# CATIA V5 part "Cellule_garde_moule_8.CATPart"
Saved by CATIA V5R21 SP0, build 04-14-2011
Part number: Moule_cellule_garde.1
Bounding box of the stored display mesh (mm): x -18 to 18, y -85 to 85, z -20 to 0
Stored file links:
  C:\Users\zerma\Pictures\Stage Stomate\Moule_4 pas utiliser\Cellule_garde_moule_8.CATPart
  Product1.CATProduct
  C:\Users\zerma\Pictures\Moule\Moule_v1.CATPart
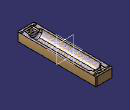
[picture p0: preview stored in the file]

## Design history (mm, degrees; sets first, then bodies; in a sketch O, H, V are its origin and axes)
Body1 (main body)
  Sketch1 on yz-plane, origin (0, 0, 0), H (0, 1, 0), V (0, 0, 1)
    line L1 (-95, -12.5) -> (95, -12.5)
    point P1 (-95, -12.5)
    line L2 (-100, -17.5) -> (100, -17.5)
    point P3 (-100, -17.5)
    line L3 (-95, -12.5) -> (-95, 0)
    point P5 (-95, 0)
    line L4 (-100, -17.5) -> (-100, 0)
    point P6 (-100, 0)
    line L5 (-95, 0) -> (-100, 0)
    point P7 (100, 0)
    point P8 (100, -17.5)
    line L6 (100, -17.5) -> (100, 0)
    point P9 (95, 0)
    line L7 (95, 0) -> (100, 0)
    point P10 (95, -12.5)
    line L8 (95, -12.5) -> (95, 0)
    distance L1 H = 12.5
    distance L1 L2 = 5
    distance L4 L3 = 5
    length L1 = 190
    length L2 = 200
    distance V L3 = 95
    horizontal: L1 H, L2 H, L5 H
    vertical: L3 V, L4 V
    symmetry: P6 P7 V, P3 P8 V, L4 L6 V, P5 P9 V, L5 L7 V, P1 P10 V, L3 L8 V
    coincidence: L5 H
  Shaft1: profile Sketch1, axis Sketch1.H, angle 360
  Sketch2 on face of Shaft1 from Sketch1.L4, origin (0, -100, 0), H (1, 0, 0), V (0, 0, 1)
    line L1 (-10, 2.5) -> (10, 2.5)
    line L2 (10, 2.5) -> (10, -2.5)
    line L3 (10, -2.5) -> (-10, -2.5)
    line L4 (-10, -2.5) -> (-10, 2.5)
    length L2 = 5
    length L1 = 20
    horizontal: L1 H, L3 H
    vertical: L2 V, L4 V
    symmetry: L3 L1 H, L4 L2 V
  Pad1: profile Sketch2, direction (0, -1, 0), length 15
  Sketch3 on face of Pad1 from Sketch2.L1, origin (0, 0, 2.5), H (1, 0, 0), V (0, 1, 0)
    circle A1 centre (0, -107.5) radius 2.5
    point P1 (0, -107.5)
    reference intersected line E1 (17.3205, -100) -> (-17.3205, -100) from face of Shaft1 from Sketch1.L4
    radius A1 = 2.5
    distance P1 E1 = 7.5
    coincidence: P1 V
  Pocket1: profile Sketch3, direction (0, 0, -1), length 5, mirrored extent
  Fillet1: radius 2, on edge [face of Pad1 from Sketch2.L4 | end face of Pad1]; edge [face of Pad1 from Sketch2.L1 | end face of Pad1]; edge [face of Pad1 from Sketch2.L3 | end face of Pad1]; edge [face of Pad1 from Sketch2.L2 | end face of Pad1]; edge [face of Pad1 from Sketch2.L2 | face of Pad1 from Sketch2.L3]; edge [face of Shaft1 from Sketch1.L4 | face of Pad1 from Sketch2.L3]; edge [face of Pad1 from Sketch2.L3 | face of Pad1 from Sketch2.L4]; edge [face of Pocket1 from Sketch3.A1 | face of Pad1 from Sketch2.L3]; edge [face of Pad1 from Sketch2.L4 | face of Pad1 from Sketch2.L1]; edge [face of Pad1 from Sketch2.L1 | face of Pad1 from Sketch2.L2]; edge [face of Shaft1 from Sketch1.L4 | face of Pad1 from Sketch2.L1]; edge [face of Shaft1 from Sketch1.L4 | face of Pad1 from Sketch2.L4]; edge [face of Shaft1 from Sketch1.L4 | face of Pad1 from Sketch2.L2]; face of Pad1 from Sketch2.L1
  Mirror1: of Pad1, Pocket1, Fillet1, about zx-plane
  Fillet2: radius 4, on edge [face of Shaft1 from Sketch1.L2 | face of Shaft1 from Sketch1.L6]; edge [face of Shaft1 from Sketch1.L4 | face of Shaft1 from Sketch1.L2]
Body2
  Sketch4 on xy-plane, origin (0, 0, 0), H (1, 0, 0), V (0, 1, 0)
    line L1 (18, 85) -> (18, -85)
    line L2 (18, -85) -> (-18, -85)
    line L3 (-18, -85) -> (-18, 85)
    line L4 (-18, 85) -> (18, 85)
    length L4 = 36
    length L1 = 170
    vertical: L1 V, L3 V
    horizontal: L2 H, L4 H
    equidistance: L1 L3 O, L2 L4 O
  Pad2: profile Sketch4, direction (0, 0, -1), length 20
  Sketch5 on end face of Pad2, origin (0, 0, -20), H (1, 0, 0), V (0, -1, 0)
    circle A1 centre (14, 79) radius 2.25
    point P1 (14, 79)
    circle A2 centre (14, -79) radius 2.25
    circle A3 centre (-14, 79) radius 2.25
    circle A4 centre (-14, -79) radius 2.25
    reference projected line E1 (18, 120) -> (18, -120) from edge [end face of Pad2 | face of Pad2 from Sketch4.L1]
    reference projected line E2 (-30, 85) -> (30, 85) from edge [end face of Pad2 | face of Pad2 from Sketch4.L2]
    radius A1 = 2.25
    distance P1 E1 = 4
    distance P1 E2 = 6
    symmetry: A1 A2 H, A1 A3 V, A3 A4 H
  Pocket2: profile Sketch5, direction (0, 0, 1), length 50, mirrored extent
  Chamfer1: length 2, angle 45, on edge [face of Pad2 from Sketch4.L4 | face of Pad2 from Sketch4.L3]; edge [end face of Pad2 | face of Pad2 from Sketch4.L4]; edge [end face of Pad2 | face of Pad2 from Sketch4.L3]; edge [face of Pad2 from Sketch4.L1 | face of Pad2 from Sketch4.L4]; edge [end face of Pad2 | face of Pad2 from Sketch4.L1]; edge [end face of Pad2 | face of Pad2 from Sketch4.L2]; edge [face of Pad2 from Sketch4.L2 | face of Pad2 from Sketch4.L1]; edge [face of Pad2 from Sketch4.L3 | face of Pad2 from Sketch4.L2]
  Body3
    Sketch6 on yz-plane, origin (0, 0, 0), H (0, 1, 0), V (0, 0, 1)
      line L1 (-61, -8) -> (61, -8)
      point P1 (-61, -8)
      point P2 (61, -8)
      line L2 (-66, -13.5) -> (66, -13.5)
      point P3 (-66, -13.5)
      point P4 (66, -13.5)
      line L3 (-61, -8) -> (-61, 0)
      point P5 (-61, 0)
      line L4 (-66, -13.5) -> (-66, 0)
      point P6 (-66, 0)
      line L5 (-61, 0) -> (-66, 0)
      point P7 (66, 0)
      point P8 (66, -13.5)
      line L6 (66, -13.5) -> (66, 0)
      point P9 (61, 0)
      line L7 (61, 0) -> (66, 0)
      point P10 (61, -8)
      line L8 (61, -8) -> (61, 0)
      distance L1 H = 8
      distance L1 L2 = 5.5
      distance L4 L3 = 5
      distance V L3 = 61
      horizontal: L1 H, L2 H, L5 H
      vertical: L3 V, L4 V
      symmetry: P6 P7 V, P3 P8 V, L4 L6 V, P5 P9 V, L5 L7 V, P1 P10 V, L3 L8 V
      coincidence: L5 H, P4 P8, P2 P10
    Shaft2: profile Sketch6, axis Sketch6.H, angle 360
    Sketch7 on face of Shaft2 from Sketch6.L4, origin (0, -66, 0), H (1, 0, 0), V (0, 0, 1)
      line L1 (-10, 2.5) -> (10, 2.5)
      line L2 (10, 2.5) -> (10, -2.5)
      line L3 (10, -2.5) -> (-10, -2.5)
      line L4 (-10, -2.5) -> (-10, 2.5)
      length L2 = 5
      length L1 = 20
      horizontal: L1 H, L3 H
      vertical: L2 V, L4 V
      symmetry: L3 L1 H, L4 L2 V
    Pad3: profile Sketch7, direction (0, -1, 0), length 15
    Sketch8 on face of Pad3 from Sketch7.L1, origin (0, 0, 2.5), H (1, 0, 0), V (0, 1, 0)
      circle A1 centre (0, -73.5) radius 2.5
      point P1 (0, -73.5)
      reference intersected line E1 (13.2665, -66) -> (-13.2665, -66) from face of Shaft2 from Sketch6.L4
      radius A1 = 2.5
      distance P1 E1 = 7.5
      coincidence: P1 V
    Pocket3: profile Sketch8, direction (0, 0, -1), length 5, mirrored extent
    Fillet3: radius 2, on edge [face of Pad3 from Sketch7.L4 | end face of Pad3]; edge [face of Pad3 from Sketch7.L1 | end face of Pad3]; edge [face of Pad3 from Sketch7.L3 | end face of Pad3]; edge [face of Pad3 from Sketch7.L2 | end face of Pad3]; edge [face of Pad3 from Sketch7.L2 | face of Pad3 from Sketch7.L3]; edge [face of Shaft2 from Sketch6.L4 | face of Pad3 from Sketch7.L3]; edge [face of Pad3 from Sketch7.L3 | face of Pad3 from Sketch7.L4]; edge [face of Pocket3 from Sketch8.A1 | face of Pad3 from Sketch7.L3]; edge [face of Pad3 from Sketch7.L4 | face of Pad3 from Sketch7.L1]; edge [face of Pad3 from Sketch7.L1 | face of Pad3 from Sketch7.L2]; edge [face of Shaft2 from Sketch6.L4 | face of Pad3 from Sketch7.L1]; edge [face of Shaft2 from Sketch6.L4 | face of Pad3 from Sketch7.L4]; edge [face of Shaft2 from Sketch6.L4 | face of Pad3 from Sketch7.L2]; face of Pad3 from Sketch7.L1
    Mirror2: of Pad3, Pocket3, Fillet3, about zx-plane
    Fillet4: radius 4, on edge [face of Shaft2 from Sketch6.L2 | face of Shaft2 from Sketch6.L6]; edge [face of Shaft2 from Sketch6.L4 | face of Shaft2 from Sketch6.L2]
  Remove1: tool Body3
  Sketch9 on face of Shaft2 from Sketch6.L3, origin (0, -61, 0), H (1, 0, 0), V (0, 0, 1)
    circle A1 centre (0, 0) radius 8
    reference projected circle E1 centre (0, 0) radius 8 from edge [face of Shaft2 from Sketch6.L3 | face of Shaft2 from Sketch6.L1]
    coincidence: A1 E1
  Pocket4: profile Sketch9, direction (0, 1, 0), up to face of Shaft2 from Sketch6.L8
  CLDGeom1 "Maillage.1"
  CLDGeom2 "Maillage.2"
